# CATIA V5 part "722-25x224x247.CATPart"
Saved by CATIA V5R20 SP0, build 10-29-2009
Part number: 722-25x224x247
Definition: NONE
Nomenclature: 722-25x224x247
Source: Unknown
Description: 722-25x224x247
Bounding box of the stored display mesh (mm): x -12.5 to 12.5, y -12.5 to 12.5, z -212 to 35
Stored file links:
  C:\Users\Utente\Desktop\IO LAVORO\3D X SITO CF\X SITO\722\722-25x224x247.CATPart
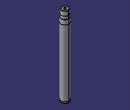
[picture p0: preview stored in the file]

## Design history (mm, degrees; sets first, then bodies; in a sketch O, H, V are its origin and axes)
Body1 "722-25x224x247" (main body)
  Solid1: solid without history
